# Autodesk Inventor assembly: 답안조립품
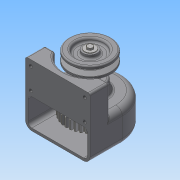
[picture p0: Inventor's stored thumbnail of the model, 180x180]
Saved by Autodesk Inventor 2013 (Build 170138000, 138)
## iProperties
Created: 2015-02
Part Number: 답안조립품
Document SubType Name: Assembly
Designer: Administrator
Author: Administrator
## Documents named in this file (14)
- C:\Documents and Settings\Administrator\바탕 화면\450214V1016\답안조립품.iam
- C:\Documents and Settings\Administrator\바탕 화면\450214V1016\1-본체.ipt
- C:\Documents and Settings\Administrator\바탕 화면\450214V1016\베어링 6001.ipt
- C:\Documents and Settings\Administrator\바탕 화면\450214V1016\축.ipt
- C:\Documents and Settings\Administrator\바탕 화면\450214V1016\키5x5.ipt
- C:\Documents and Settings\Administrator\바탕 화면\450214V1016\스퍼기어.ipt
- C:\Documents and Settings\Administrator\바탕 화면\450214V1016\축커버.ipt
- C:\Documents and Settings\Administrator\바탕 화면\450214V1016\오일실.ipt
- C:\Documents and Settings\Administrator\바탕 화면\450214V1016\M3x0.5.ipt
- C:\Documents and Settings\Administrator\바탕 화면\450214V1016\키4x4.ipt
- C:\Documents and Settings\Administrator\바탕 화면\450214V1016\4-벨트풀리.ipt
- C:\Documents and Settings\Administrator\바탕 화면\450214V1016\와샤.ipt
- C:\Documents and Settings\Administrator\바탕 화면\450214V1016\M5x0.8.ipt
- M5x0.8.ipt
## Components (7 placed, 4 different names)
1. 1-본체:1
2. 4-벨트풀리:1 — 각도:3
3. M5x0.8:1
4. M3x0.5:1
5. M3x0.5:2
6. M3x0.5:3
7. M3x0.5:4
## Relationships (1: Angle 1)
- 각도:3 [Angle]: 4-벨트풀리:1
